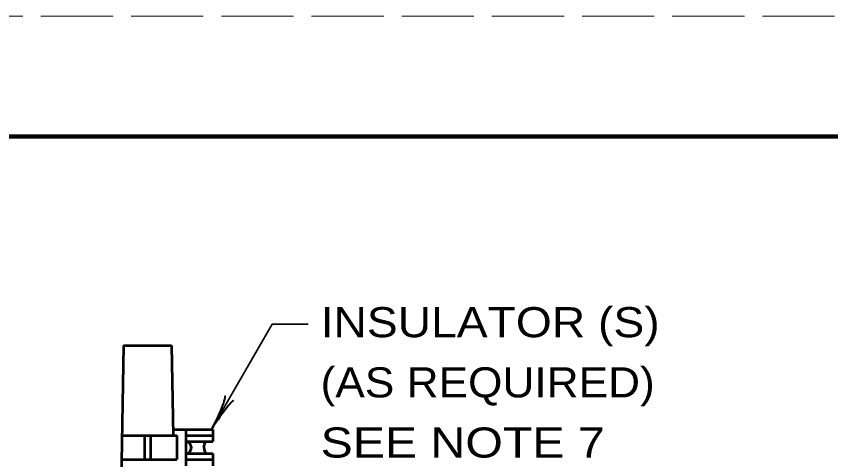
# Model space of a CAD drawing. Extents: x 12366 to 13046, y 9129 to 9570.
# Drawn here: x 12453.9 to 12521.7, y 9532.7 to 9569.5 of the extents above; entities that cross this region are included whole.
import ezdxf

# ---------------------------------------------------------------- set-up
doc = ezdxf.new("R2010")
doc.units = 0
doc.linetypes.add('LONG_DASHED', pattern=[7.5, 6, -1.5])
doc.layers.add('1', color=7, linetype='Continuous', lineweight=53)
doc.layers.add('61', color=7, linetype='Continuous', lineweight=35)

msp = doc.modelspace()

# ---------------------------------------------------------------- linework, layer by layer
at = {"layer": '1'}
for p, q in [((12462.852, 9542.164), (12460.844, 9427.165)), ((12462.852, 9542.164), (12460.844, 9427.137)), ((12462.852, 9542.164), (12460.844, 9427.133)), ((12462.852, 9542.164), (12466.852, 9542.164)), ((12462.852, 9542.164), (12466.852, 9542.164)), ((12462.852, 9542.164), (12466.852, 9542.164)), ((12466.852, 9542.164), (12466.982, 9534.709)), ((12466.852, 9542.164), (12466.981, 9534.735)), ((12466.852, 9542.164), (12466.982, 9534.681)), ((12466.973, 9535.189), (12468.026, 9535.189)), ((12468.026, 9535.189), (12468.026, 9532.189)), ((12468.026, 9535.189), (12470.276, 9535.189)), ((12470.276, 9535.189), (12470.276, 9534.189)), ((12462.721, 9534.689), (12466.98, 9534.689)), ((12464.6, 9534.695), (12464.6, 9532.695)), ((12465.1, 9534.695), (12465.1, 9532.695)), ((12466.686, 9534.689), (12467.276, 9534.689)), ((12467.276, 9534.689), (12467.276, 9532.689)), ((12468.026, 9534.689), (12470.276, 9534.689)), ((12468.026, 9534.189), (12470.276, 9534.189)), ((12462.721, 9532.689), (12467.276, 9532.689)), ((12468.026, 9533.189), (12470.276, 9533.189)), ((12468.026, 9532.689), (12470.276, 9532.689)), ((12470.276, 9533.189), (12470.276, 9532.189))]:
    msp.add_line(p, q, dxfattribs=at)
at = {"layer": '1', "lineweight": 35}
msp.add_lwpolyline([(12470.223, 9535.297), (12475.223, 9543.957), (12478.223, 9543.957)], dxfattribs=at)
at = {"layer": '1'}
for centre, radius, start, end in [((12467.996, 9533.689), 0.501, 273.51208, 86.48792), ((12470.36, 9533.713), 0.821, 144.51909, 219.31134)]:
    msp.add_arc(centre, radius, start, end, dxfattribs=at)
at = {"layer": '1', "lineweight": 40}
for centre, major_axis, ratio, start_param, end_param in [((12470.53, 9536.38), (-0.758, -1.625), 0.122415, 0.896353, 3.141593), ((12470.967, 9536.162), (1.03, 1.433), 0.07063, 6.282307, 8.559703)]:
    msp.add_ellipse(centre, major_axis=major_axis, ratio=ratio, start_param=start_param, end_param=end_param, dxfattribs=at)
at = {"layer": '61', "linetype": 'LONG_DASHED', "lineweight": 13}
msp.add_line((12365.992, 9569.533), (13046.012, 9569.533), dxfattribs=at)
at = {"layer": '61', "lineweight": 158}
msp.add_lwpolyline([(13035.032, 9559.533), (12395.992, 9559.533), (12395.992, 9139.513)], dxfattribs=at)

# ---------------------------------------------------------------- texts
at = {"layer": '1'}
for s, width, p in [('INSULATOR (S)', 1.15, (12479.245, 9542.863)), ('(AS REQUIRED)', 1.1, (12479.245, 9537.863)), ('SEE NOTE 7', 1.2, (12479.245, 9532.863))]:
    msp.add_text(s, height=2.5, dxfattribs=dict(at, width=width)).set_placement(p)

doc.saveas('drawing.dxf')
